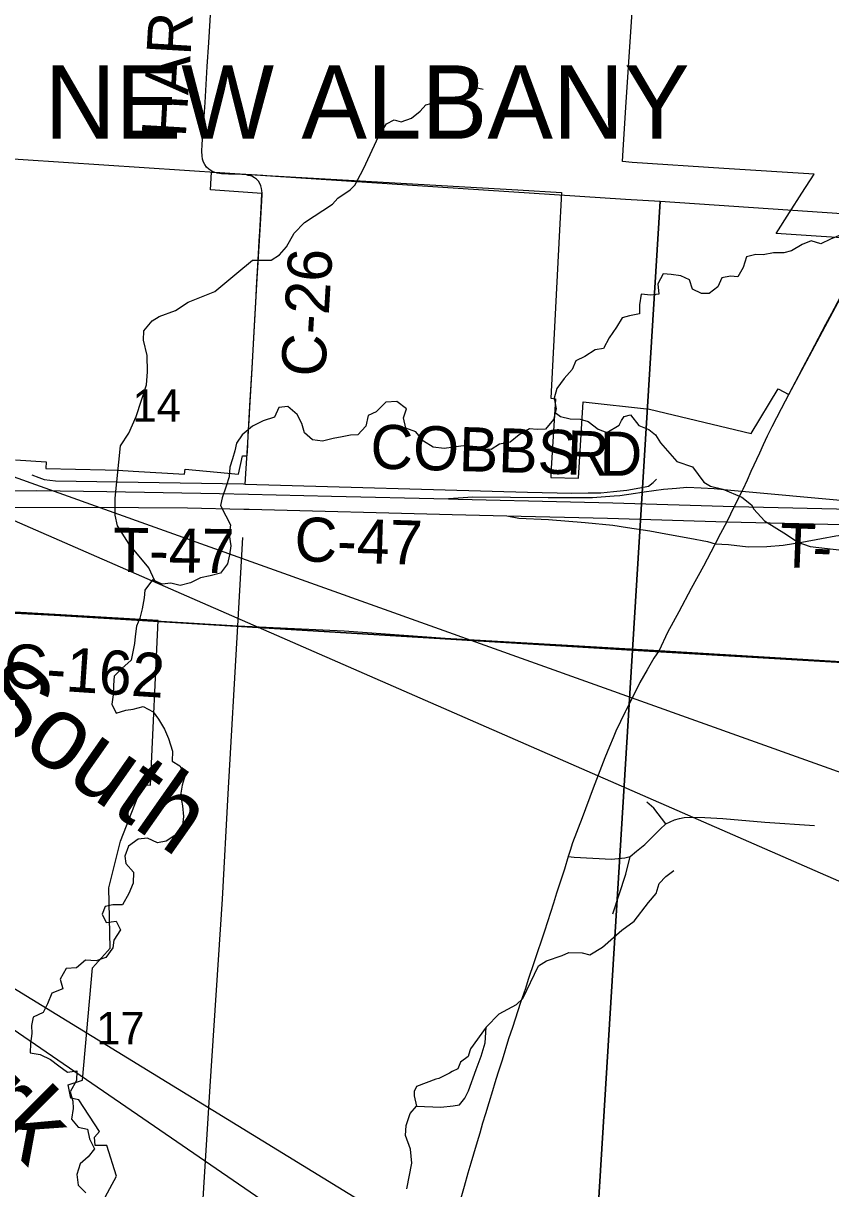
# Model space of a CAD drawing. Extents: x 0 to 91.3, y -0.7 to 22.
# Drawn here: x 6.125 to 7.164, y 16.725 to 18.226 of the extents above; entities that cross this region are included whole.
import ezdxf

# ---------------------------------------------------------------- set-up
doc = ezdxf.new("R2010")
doc.units = 0
for name, color, linetype in [('GM_X_Corporation', 7, 'Continuous'), ('GM_X_Corporation_Text', 7, 'Continuous'), ('GM_X_County_Road', 7, 'Continuous'), ('GM_X_County_Road_Text', 7, 'Continuous'), ('GM_X_Interchange_Ramps', 7, 'Continuous'), ('GM_X_Major_River', 7, 'Continuous'), ('GM_X_Major_River_Text', 7, 'Continuous'), ('GM_X_Minor_Lake', 7, 'Continuous'), ('GM_X_Minor_River', 7, 'Continuous'), ('GM_X_Section_Text', 7, 'Continuous'), ('GM_X_State_Route', 7, 'Continuous'), ('GM_X_Township_Road', 7, 'Continuous'), ('GM_X_Township_Road_Text', 7, 'Continuous'), ('SH_Text', 7, 'Continuous')]:
    doc.layers.add(name, color=color, linetype=linetype)

msp = doc.modelspace()

# ---------------------------------------------------------------- linework, layer by layer
at = {"layer": 'GM_X_Corporation'}
for points in [[(6.115, 17.6633), (6.1545, 17.6609), (6.154, 17.6524), (6.2304, 17.6504), (6.2466, 17.65), (6.2663, 17.6488), (6.3327, 17.645), (6.3332, 17.6514), (6.4022, 17.6449), (6.4072, 17.6688), (6.413, 17.6685), (6.4138, 17.682), (6.4146, 17.6971), (6.4156, 17.7136), (6.4165, 17.7307), (6.4194, 17.7809), (6.4221, 17.8288), (6.4247, 17.8744), (6.4253, 17.8849), (6.4273, 17.921), (6.4287, 17.945), (6.4294, 17.9577), (6.4311, 17.9875), (6.4322, 18.0066), (6.3659, 18.0113), (6.3674, 18.0339), (6.4335, 18.0301), (6.4383, 18.0298), (6.6935, 18.0151), (6.7616, 18.0112), (6.8178, 18.0078), (6.8149, 17.9511), (6.8041, 17.7429), (6.8101, 17.7422), (6.8041, 17.6453), (6.8041, 17.6442), (6.8038, 17.6405), (6.8398, 17.6397), (6.8455, 17.7383), (6.931, 17.7287), (7.0619, 17.6975), (7.0965, 17.7548), (7.1102, 17.7478), (7.2165, 17.9469), (7.0938, 17.9548), (7.1113, 17.9822), (7.1271, 18.0068), (7.1429, 18.0314), (7.0266, 18.0388), (6.9086, 18.0464), (6.8962, 18.0478), (6.8971, 18.0622), (6.9007, 18.1177), (6.9141, 18.3252)], [(6.2162, 16.6875), (6.2451, 16.7407), (6.2327, 16.7805), (6.2175, 16.7804), (6.2165, 16.7911), (6.2233, 16.7982), (6.1965, 16.8393), (6.1864, 16.8414), (6.1829, 16.8584), (6.2011, 16.8645), (6.214, 17.009), (6.2334, 17.0305), (6.2368, 17.0344), (6.2369, 17.0344), (6.2349, 17.1124), (6.25, 17.1722), (6.2725, 17.2294), (6.2786, 17.2449), (6.2886, 17.2443), (6.2985, 17.4564), (6.0623, 17.4704)]]:
    msp.add_lwpolyline(points, dxfattribs=at)
for points in [[(5.9168, 18.0638), (6.3846, 18.0329), (6.9002, 17.9991), (6.9448, 17.9966), (6.9092, 17.4181), (5.8879, 17.4801)], [(6.9448, 17.9966), (7.4187, 17.9645), (7.6912, 17.9463), (7.9506, 17.929), (7.9172, 17.3589), (6.9092, 17.4181)], [(5.8879, 17.4801), (6.9092, 17.4181), (6.8465, 16.3992), (5.8298, 16.4755)], [(6.9092, 17.4181), (7.9172, 17.3589), (7.8571, 16.3365), (6.8465, 16.3992)]]:
    msp.add_lwpolyline(points, close=True, dxfattribs=at)
at = {"layer": 'GM_X_County_Road'}
for p, q in [((6.4107, 17.6323), (6.4131, 17.6723)), ((6.3023, 17.4556), (6.4013, 17.4498))]:
    msp.add_line(p, q, dxfattribs=at)
for points in [[(6.3746, 18.0328), (6.3737, 18.033), (6.3716, 18.0336), (6.3675, 18.0351), (6.3636, 18.0378), (6.3609, 18.0403), (6.3587, 18.0436), (6.3571, 18.0467), (6.3558, 18.0507), (6.3551, 18.055), (6.3547, 18.0604), (6.3553, 18.07), (6.3571, 18.0936), (6.3592, 18.1238), (6.3616, 18.17), (6.3636, 18.2011), (6.3664, 18.2435), (6.3702, 18.3207)], [(6.4145, 18.0298), (6.4125, 18.0303), (6.4061, 18.031), (6.3979, 18.0314), (6.389, 18.0315), (6.38, 18.032), (6.3746, 18.0328)], [(6.4322, 18.0095), (6.4321, 18.0104), (6.4317, 18.013), (6.4308, 18.0164), (6.4294, 18.0195), (6.4277, 18.0223), (6.425, 18.0248), (6.4226, 18.0265), (6.4191, 18.0288), (6.4155, 18.0296), (6.4145, 18.0298)], [(6.4131, 17.6723), (6.4139, 17.6854), (6.4167, 17.7328), (6.4198, 17.782), (6.4259, 17.8969), (6.4304, 17.9671), (6.4325, 18.0047), (6.4325, 18.0079), (6.4322, 18.0095)], [(7.1765, 17.8732), (7.176, 17.8723), (7.1653, 17.8521), (7.1576, 17.8379), (7.1385, 17.8015), (7.1283, 17.7822), (7.1245, 17.7751)], [(7.1245, 17.7751), (7.1222, 17.7706), (7.1145, 17.7562), (7.1107, 17.749)], [(7.1107, 17.749), (7.1003, 17.7292), (7.0885, 17.7058), (7.0824, 17.6941), (7.0774, 17.6829), (7.0725, 17.672), (7.0615, 17.6484), (7.0565, 17.6371), (7.051, 17.6251), (7.0497, 17.6225), (7.0398, 17.6034), (7.0303, 17.5836), (7.0225, 17.5687), (7.0157, 17.5554), (7.0147, 17.5534), (7.0005, 17.5267), (6.9848, 17.4976)], [(6.831, 17.6204), (6.8519, 17.6208), (6.8684, 17.6211), (6.8846, 17.6225), (6.9017, 17.6245), (6.9184, 17.6273), (6.9297, 17.6295), (6.9357, 17.6341), (6.9399, 17.6387)], [(6.4107, 17.6323), (6.7741, 17.6219), (6.831, 17.6204)], [(6.9848, 17.4976), (6.9686, 17.4676), (6.954, 17.441), (6.9435, 17.4179)], [(6.0946, 17.4672), (6.1055, 17.4666), (6.1992, 17.4616), (6.3023, 17.4556)], [(6.3441, 16.5128), (6.3491, 16.5947), (6.3656, 16.8567), (6.3814, 17.0978), (6.3885, 17.2334), (6.4013, 17.4498)], [(6.4013, 17.4498), (6.538, 17.4432), (6.6681, 17.4339), (6.833, 17.4243)], [(6.833, 17.4243), (6.9435, 17.4179), (7.0214, 17.4132)], [(6.9435, 17.4179), (6.9367, 17.4078), (6.9281, 17.393), (6.9186, 17.3768), (6.9089, 17.3575), (6.9004, 17.3405), (6.8995, 17.3388)], [(7.0214, 17.4132), (7.1002, 17.4084), (7.2619, 17.3986), (7.4112, 17.39), (8.3263, 17.3397), (8.5262, 17.3288), (8.8216, 17.3124), (8.9, 17.3095)], [(6.8995, 17.3388), (6.8878, 17.314), (6.8843, 17.3055), (6.8794, 17.2943), (6.8734, 17.2797), (6.8584, 17.2406), (6.8442, 17.2024), (6.832, 17.1701), (6.8289, 17.1604), (6.8264, 17.1525), (6.8217, 17.1363), (6.8114, 17.1054), (6.8073, 17.0925), (6.7957, 17.0564), (6.7826, 17.0171), (6.775, 16.9942), (6.7712, 16.9827), (6.7651, 16.9644), (6.7545, 16.9325), (6.7496, 16.9177), (6.7412, 16.8903), (6.7359, 16.8735), (6.732, 16.8611), (6.7288, 16.8508), (6.7243, 16.8355), (6.7197, 16.821), (6.716, 16.8091), (6.7124, 16.7963), (6.7091, 16.7851), (6.7044, 16.7692), (6.7011, 16.7578), (6.6972, 16.7445), (6.6924, 16.7276), (6.6872, 16.7094)]]:
    msp.add_lwpolyline(points, dxfattribs=at)
at = {"layer": 'GM_X_Interchange_Ramps'}
for points in [[(7.0497, 17.6225), (7.0358, 17.6241), (7.0142, 17.6262), (6.9975, 17.6271), (6.9792, 17.6276), (6.9656, 17.6266), (6.949, 17.6251), (6.9243, 17.6219), (6.913, 17.62), (6.8928, 17.6171), (6.8855, 17.6166), (6.8577, 17.6146), (6.8006, 17.6146), (6.7036, 17.6152), (6.6723, 17.6131)], [(7.4118, 17.5942), (7.3985, 17.5971), (7.3279, 17.599), (7.2725, 17.6018), (7.2137, 17.6069), (7.1768, 17.611), (7.0497, 17.6225)], [(6.7472, 17.5914), (6.7629, 17.5882), (6.8008, 17.5866), (6.8483, 17.5829), (6.8838, 17.5793), (6.9025, 17.5762), (6.9313, 17.5721), (6.9522, 17.568), (6.9831, 17.5624), (7.0056, 17.5581), (7.0157, 17.5554)], [(7.0157, 17.5554), (7.0325, 17.5545), (7.058, 17.5516), (7.082, 17.5518), (7.103, 17.5537), (7.127, 17.5576), (7.1523, 17.5623), (7.1706, 17.5654), (7.1955, 17.5687), (7.2094, 17.5701), (7.2466, 17.5708), (7.2877, 17.571), (7.4209, 17.5708), (7.4356, 17.5734)]]:
    msp.add_lwpolyline(points, dxfattribs=at)
at = {"layer": 'GM_X_Major_River'}
for points in [[(7.1765, 17.9527), (7.1639, 17.9475), (7.1514, 17.9415), (7.1389, 17.9453), (7.1275, 17.9408), (7.1138, 17.9325), (7.104, 17.9299), (7.0907, 17.9299), (7.0774, 17.9273), (7.0679, 17.9277), (7.0558, 17.9248), (7.0516, 17.9111), (7.0447, 17.899), (7.0352, 17.8998), (7.0242, 17.898), (7.0189, 17.8862), (7.0079, 17.8776), (6.998, 17.8776), (6.9863, 17.8833), (6.9825, 17.8951), (6.9712, 17.9005), (6.9587, 17.902), (6.9484, 17.9032), (6.9416, 17.8903), (6.943, 17.8767), (6.9328, 17.8756), (6.9203, 17.8768), (6.9183, 17.8631), (6.9179, 17.8514), (6.9054, 17.8488), (6.8959, 17.8465), (6.8883, 17.8344), (6.8791, 17.8204)], [(6.8791, 17.8204), (6.8719, 17.8068), (6.8612, 17.805), (6.8479, 17.7967), (6.8362, 17.791), (6.8316, 17.7797), (6.8213, 17.768), (6.8118, 17.7551), (6.8083, 17.743), (6.8109, 17.7293), (6.8075, 17.7153), (6.7972, 17.7029), (6.7862, 17.7025), (6.7767, 17.7033), (6.7634, 17.6958), (6.7516, 17.686), (6.738, 17.6838), (6.7273, 17.6766), (6.7137, 17.6778), (6.7038, 17.6805), (6.6913, 17.6813), (6.6792, 17.6798), (6.6667, 17.678), (6.6526, 17.6799), (6.6402, 17.6876), (6.6304, 17.6997), (6.6175, 17.7043), (6.6145, 17.7176), (6.6183, 17.729), (6.6059, 17.7385), (6.5918, 17.7378), (6.5793, 17.7253), (6.569, 17.7204), (6.5659, 17.7068), (6.5557, 17.6955), (6.5462, 17.6951), (6.5356, 17.6929), (6.5238, 17.691), (6.5101, 17.6873), (6.4973, 17.6892), (6.487, 17.6984), (6.4833, 17.7102), (6.4773, 17.7219), (6.4656, 17.7322), (6.4538, 17.7307), (6.4485, 17.7186), (6.4337, 17.7138), (6.42, 17.707), (6.4067, 17.6957), (6.3994, 17.6851), (6.3971, 17.6749), (6.3944, 17.6646), (6.391, 17.654), (6.3898, 17.6415), (6.3863, 17.6294), (6.381, 17.6146), (6.379, 17.6048), (6.3858, 17.5915), (6.3918, 17.5797), (6.3899, 17.5668), (6.3921, 17.5528), (6.3902, 17.5411), (6.3878, 17.5293), (6.3787, 17.5176), (6.3654, 17.5139), (6.3533, 17.5116), (6.3404, 17.5049), (6.3271, 17.5015), (6.315, 17.5046), (6.3036, 17.5035), (6.2915, 17.5088), (6.2816, 17.4956), (6.2804, 17.4857), (6.2781, 17.4714), (6.275, 17.4596), (6.2708, 17.449), (6.2692, 17.4361), (6.268, 17.4267), (6.2661, 17.416), (6.2638, 17.4054), (6.252, 17.3949), (6.2421, 17.3847), (6.2409, 17.3733), (6.2405, 17.3608), (6.2389, 17.3487), (6.2446, 17.3373), (6.2571, 17.341), (6.2666, 17.3425), (6.2795, 17.3459), (6.2923, 17.339), (6.2991, 17.3295), (6.3067, 17.3166), (6.3119, 17.3044), (6.3172, 17.2881), (6.3167, 17.2752), (6.3266, 17.2695), (6.3334, 17.2573), (6.3295, 17.2444), (6.3272, 17.2315), (6.3298, 17.2179), (6.3313, 17.2039)], [(6.3313, 17.2039), (6.3301, 17.1925), (6.3213, 17.1804), (6.3088, 17.1721), (6.2978, 17.1702), (6.2849, 17.176), (6.2728, 17.1749), (6.2606, 17.1658), (6.2556, 17.153), (6.2571, 17.1435), (6.2669, 17.1324), (6.2665, 17.1184), (6.2608, 17.1048), (6.2527, 17.0904), (6.2402, 17.0901), (6.2304, 17.0882), (6.2265, 17.0784), (6.2318, 17.0677), (6.2447, 17.0692), (6.2503, 17.0582), (6.2416, 17.045), (6.2404, 17.0351), (6.2313, 17.0223), (6.2187, 17.0181), (6.2051, 17.0189), (6.1933, 17.0091), (6.18, 17.0084), (6.1724, 16.9944), (6.1761, 16.9823), (6.1617, 16.9766), (6.156, 16.9626), (6.1506, 16.9517), (6.1377, 16.9456), (6.1354, 16.935), (6.1361, 16.9248), (6.1342, 16.9115), (6.1337, 16.8998), (6.1466, 16.8975), (6.1599, 16.8913), (6.1708, 16.883), (6.1818, 16.875), (6.1939, 16.8764), (6.1935, 16.8639), (6.1855, 16.8495), (6.1889, 16.8374), (6.1892, 16.8279), (6.1872, 16.8143), (6.1955, 16.804), (6.2077, 16.8013), (6.2103, 16.7891), (6.2167, 16.7762), (6.2083, 16.7656), (6.198, 16.7566), (6.1938, 16.743), (6.1956, 16.7293), (6.2055, 16.7194)]]:
    msp.add_lwpolyline(points, dxfattribs=at)
at = {"layer": 'GM_X_Minor_Lake'}
for points in [[(6.7208, 16.9327), (6.7005, 16.9048), (6.6998, 16.9021), (6.6978, 16.8949), (6.6879, 16.8878), (6.6841, 16.8791), (6.6772, 16.8757), (6.6734, 16.8735), (6.6598, 16.8667), (6.656, 16.8656), (6.6434, 16.8611), (6.6313, 16.8563), (6.6282, 16.8499), (6.6282, 16.8442), (6.6311, 16.8309)], [(6.6311, 16.8309), (6.6626, 16.8296), (6.6781, 16.8314), (6.6865, 16.8328), (6.6934, 16.8411), (6.698, 16.8506), (6.708, 16.8782), (6.7145, 16.8952), (6.7195, 16.9126), (6.7208, 16.9327)]]:
    msp.add_lwpolyline(points, dxfattribs=at)
at = {"layer": 'GM_X_Minor_River'}
for points in [[(6.2945, 17.5075), (6.2866, 17.5242), (6.2614, 17.5547), (6.2463, 17.5786), (6.2434, 17.5923), (6.2431, 17.6139), (6.2503, 17.6814), (6.261, 17.6976), (6.2703, 17.7192), (6.2834, 17.76), (6.285, 17.7767), (6.2843, 17.7979), (6.2799, 17.8177), (6.28, 17.8298), (6.291, 17.8426), (6.2998, 17.8479), (6.3207, 17.8557), (6.3374, 17.8666), (6.3716, 17.8801), (6.3998, 17.9038), (6.42, 17.9207), (6.4439, 17.9206), (6.4549, 17.9274), (6.4637, 17.9379), (6.4736, 17.9553), (6.487, 17.9689), (6.5228, 17.9929), (6.53, 18.0005), (6.5456, 18.011), (6.5517, 18.0174), (6.5628, 18.0382), (6.5824, 18.0809), (6.5923, 18.0964), (6.6022, 18.1013), (6.6113, 18.0989), (6.6246, 18.1034), (6.6357, 18.1124), (6.6429, 18.1207), (6.6626, 18.1259), (6.6771, 18.1258), (6.6846, 18.1281), (6.7025, 18.1409), (6.7075, 18.1431), (6.7169, 18.1408)], [(6.8097, 17.7246), (6.8166, 17.7193), (6.8287, 17.7162), (6.8416, 17.7158), (6.8522, 17.7127), (6.865, 17.7031), (6.876, 17.6985), (6.8919, 17.7079), (6.895, 17.7139), (6.8985, 17.7192), (6.9064, 17.7214), (6.9173, 17.7077), (6.9302, 17.7027), (6.9385, 17.6958), (6.9453, 17.6852), (6.966, 17.6612), (6.9864, 17.6546), (7.0007, 17.6348), (7.0094, 17.6294), (7.0253, 17.6256), (7.0499, 17.6152), (7.0624, 17.6056), (7.0654, 17.5999), (7.0789, 17.5847), (7.1073, 17.5674), (7.122, 17.5575), (7.1379, 17.5517), (7.1784, 17.5473)], [(6.7208, 16.9327), (6.7376, 16.9501), (6.7596, 16.9621), (6.768, 16.9696), (6.788, 17.0116), (6.7982, 17.0183), (6.8184, 17.025), (6.8271, 17.0288), (6.8445, 17.0287), (6.854, 17.026), (6.8707, 17.0357), (6.8955, 17.0576), (6.9111, 17.0692), (6.9298, 17.0934), (6.9397, 17.1051), (6.9436, 17.1176), (6.952, 17.127), (6.9623, 17.1345)], [(6.6188, 16.7244), (6.625, 16.7574), (6.6232, 16.7756), (6.6169, 16.7934), (6.6177, 16.8063), (6.6231, 16.8214), (6.6311, 16.8309)]]:
    msp.add_lwpolyline(points, dxfattribs=at)
at = {"layer": 'GM_X_State_Route'}
for points in [[(5.5943, 17.5864), (5.7563, 17.6003), (5.8002, 17.604), (5.8904, 17.6119), (5.9627, 17.6172), (5.9805, 17.6185), (6.0166, 17.6205), (6.0705, 17.6229), (6.1063, 17.6237), (6.1423, 17.624), (6.2325, 17.6227), (6.3777, 17.6201), (6.4147, 17.6193)], [(6.4147, 17.6193), (6.5219, 17.6168), (6.6723, 17.6131), (6.6849, 17.6128), (6.8294, 17.6094), (6.884, 17.6079), (7.0398, 17.6034), (7.2094, 17.5996), (7.3717, 17.5953), (7.4118, 17.5942), (7.5344, 17.5911), (7.7514, 17.5852), (7.9683, 17.5793), (8.1766, 17.5745), (8.2816, 17.5714), (8.4129, 17.5685), (8.5578, 17.5648), (8.7192, 17.5607), (8.864, 17.5567), (8.9, 17.5553)], [(5.7505, 17.5792), (5.8898, 17.5913), (5.9624, 17.5978), (6.0395, 17.6027), (6.0985, 17.6026), (6.2731, 17.602), (6.3364, 17.6018), (6.4089, 17.6), (6.4159, 17.5998)], [(6.4159, 17.5998), (6.677, 17.5931), (6.7472, 17.5914), (6.8769, 17.5882), (7.0303, 17.5836), (7.2161, 17.5792), (7.4145, 17.5739), (7.4356, 17.5734), (8.0357, 17.5587), (8.843, 17.5339), (8.9, 17.5321)]]:
    msp.add_lwpolyline(points, dxfattribs=at)
at = {"layer": 'GM_X_Township_Road'}
msp.add_line((6.4013, 17.4498), (6.4075, 17.5636), dxfattribs=at)
for points in [[(6.136, 17.6442), (6.1448, 17.6405), (6.1519, 17.638), (6.1665, 17.6365), (6.273, 17.6347), (6.4085, 17.6324), (6.4107, 17.6323)], [(6.9522, 17.1946), (6.9366, 17.215), (6.9274, 17.2226)], [(6.8264, 17.1525), (6.8341, 17.1519), (6.8579, 17.1502), (6.8822, 17.149), (6.8991, 17.151), (6.9061, 17.1527), (6.9143, 17.1593), (6.925, 17.1682), (6.9349, 17.178), (6.9445, 17.1876), (6.9522, 17.1946), (6.9631, 17.1996), (6.9695, 17.2017), (6.9754, 17.2029), (6.987, 17.2034), (7.0023, 17.2027), (7.0252, 17.2013), (7.0796, 17.1968), (7.1432, 17.1925)], [(6.8837, 17.0788), (6.9004, 17.1296), (6.9061, 17.1527)]]:
    msp.add_lwpolyline(points, dxfattribs=at)
at = {"layer": 'SH_Text'}
for points in [[(9.2012, 16.2343), (5.4038, 17.8952), (9.2012, 16.5366)], [(9.2012, 14.8079), (5.3743, 17.4358), (9.2012, 15.0876)]]:
    msp.add_lwpolyline(points, close=True, dxfattribs=at)

# ---------------------------------------------------------------- texts
at = {"layer": 'GM_X_Corporation_Text'}
msp.add_text('NEW ALBANY', height=0.0947, rotation=0, dxfattribs=at).set_placement((6.1523, 18.0769))
at = {"layer": 'GM_X_County_Road_Text'}
for s, height, rotation, p in [('HARRISON RD', 0.056818, 86.6573, (6.3341, 18.0781)), ('C-26', 0.05682, 86.572, (6.5133, 17.7693)), ('COBBS', 0.05682, 358.3216, (6.5711, 17.6524)), ('R', 0.0568, 357.7943, (6.8234, 17.6448)), ('D', 0.0568, 359.7558, (6.8667, 17.643)), ('C-47', 0.05682, 358.286, (6.4734, 17.533)), ('C-162', 0.05682, 356.1504, (6.0986, 17.3708))]:
    msp.add_text(s, height=height, rotation=rotation, dxfattribs=at).set_placement(p)
at = {"layer": 'GM_X_Major_River_Text'}
for s, height, rotation, p in [('South', 0.0947, 324.9987, (6.0514, 17.3406)), ('Fork', 0.0947, 314.9954, (5.9522, 16.9307)), ('Licking', 0.09471, 314.9945, (5.9464, 16.7478))]:
    msp.add_text(s, height=height, rotation=rotation, dxfattribs=at).set_placement(p)
at = {"layer": 'GM_X_Section_Text'}
for s, p in [('14', (6.2655, 17.7125)), ('17', (6.2189, 16.9106))]:
    msp.add_text(s, height=0.04186, rotation=0, dxfattribs=at).set_placement(p)
at = {"layer": 'GM_X_Township_Road_Text'}
for s, height, rotation, p in [('T-47', 0.05682, 359.2931, (6.2403, 17.5193)), ('T', 0.0568, 357.7066, (7.0975, 17.5255)), ('-', 0.0568, 357.603, (7.1399, 17.5238))]:
    msp.add_text(s, height=height, rotation=rotation, dxfattribs=at).set_placement(p)

doc.saveas('drawing.dxf')
